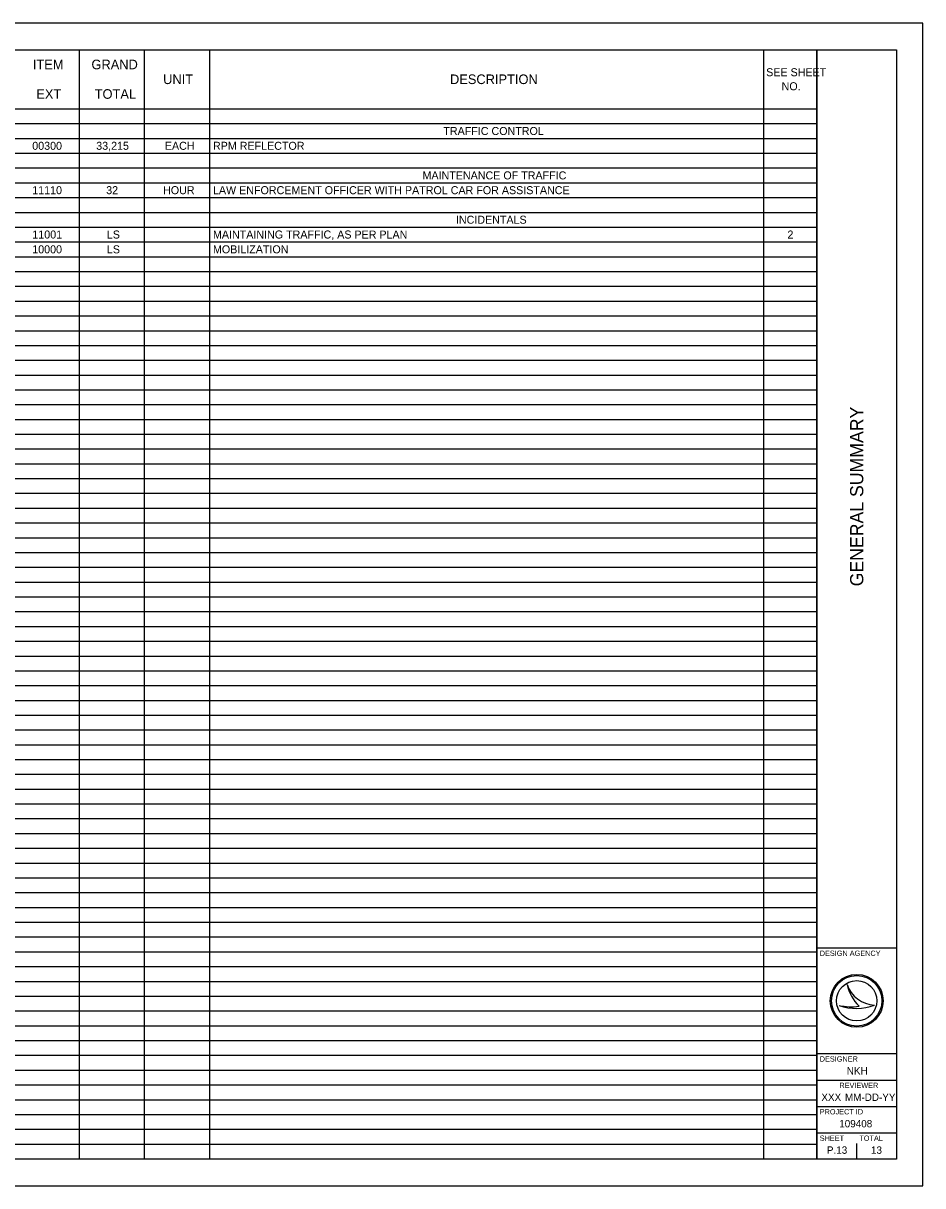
# Model space of a CAD drawing. Extents: x 0 to 34, y 0 to 22.
# Drawn here: x 16.97 to 34, y 0 to 22 of the extents above; entities that cross this region are included whole.
import ezdxf

# ---------------------------------------------------------------- set-up
doc = ezdxf.new("R2010")
doc.units = 0
for name, color, linetype in [('Default', 7, 'Continuous'), ('SH_Border', 7, 'Continuous'), ('SH_Cut_Line', 7, 'Continuous'), ('SH_Data', 7, 'Continuous')]:
    doc.layers.add(name, color=color, linetype=linetype)

msp = doc.modelspace()

# ---------------------------------------------------------------- linework, layer by layer
at = {"layer": 'Default'}
for p, q in [((1.5, 21.5), (31.99, 21.5)), ((18.029, 21.5), (18.029, 0.51)), ((19.264, 21.5), (19.264, 0.51)), ((20.498, 21.5), (20.498, 0.51)), ((30.985, 21.5), (30.985, 0.51)), ((31.99, 21.5), (31.99, 0.51)), ((1.5, 20.381), (31.99, 20.381)), ((1.5, 20.101), (31.99, 20.101)), ((1.5, 19.821), (31.99, 19.821)), ((1.5, 19.541), (31.99, 19.541)), ((1.5, 19.261), (31.99, 19.261)), ((1.5, 18.981), (31.99, 18.981)), ((1.5, 18.701), (31.99, 18.701)), ((1.5, 18.421), (31.99, 18.421)), ((1.5, 18.142), (31.99, 18.142)), ((1.5, 17.862), (31.99, 17.862)), ((1.5, 17.582), (31.99, 17.582)), ((1.5, 17.302), (31.99, 17.302)), ((1.5, 17.022), (31.99, 17.022)), ((1.5, 16.742), (31.99, 16.742)), ((1.5, 16.462), (31.99, 16.462)), ((1.5, 16.182), (31.99, 16.182)), ((1.5, 15.903), (31.99, 15.903)), ((1.5, 15.623), (31.99, 15.623)), ((1.5, 15.343), (31.99, 15.343)), ((1.5, 15.063), (31.99, 15.063)), ((1.5, 14.783), (31.99, 14.783)), ((1.5, 14.503), (31.99, 14.503)), ((1.5, 14.223), (31.99, 14.223)), ((1.5, 13.943), (31.99, 13.943)), ((1.5, 13.664), (31.99, 13.664)), ((1.5, 13.384), (31.99, 13.384)), ((1.5, 13.104), (31.99, 13.104)), ((1.5, 12.824), (31.99, 12.824)), ((1.5, 12.544), (31.99, 12.544)), ((1.5, 12.264), (31.99, 12.264)), ((1.5, 11.984), (31.99, 11.984)), ((1.5, 11.705), (31.99, 11.705)), ((1.5, 11.425), (31.99, 11.425)), ((1.5, 11.145), (31.99, 11.145)), ((1.5, 10.865), (31.99, 10.865)), ((1.5, 10.585), (31.99, 10.585)), ((1.5, 10.305), (31.99, 10.305)), ((1.5, 10.025), (31.99, 10.025)), ((1.5, 9.745), (31.99, 9.745)), ((1.5, 9.466), (31.99, 9.466)), ((1.5, 9.186), (31.99, 9.186)), ((1.5, 8.906), (31.99, 8.906)), ((1.5, 8.626), (31.99, 8.626)), ((1.5, 8.346), (31.99, 8.346)), ((1.5, 8.066), (31.99, 8.066)), ((1.5, 7.786), (31.99, 7.786)), ((1.5, 7.506), (31.99, 7.506)), ((1.5, 7.227), (31.99, 7.227)), ((1.5, 6.947), (31.99, 6.947)), ((1.5, 6.667), (31.99, 6.667)), ((1.5, 6.387), (31.99, 6.387)), ((1.5, 6.107), (31.99, 6.107)), ((1.5, 5.827), (31.99, 5.827)), ((1.5, 5.547), (31.99, 5.547)), ((1.5, 5.267), (31.99, 5.267)), ((1.5, 4.988), (31.99, 4.988)), ((1.5, 4.708), (31.99, 4.708)), ((1.5, 4.428), (31.99, 4.428)), ((1.5, 4.148), (31.99, 4.148)), ((1.5, 3.868), (31.99, 3.868)), ((1.5, 3.588), (31.99, 3.588)), ((1.5, 3.308), (31.99, 3.308)), ((1.5, 3.028), (31.99, 3.028)), ((1.5, 2.749), (31.99, 2.749)), ((1.5, 2.469), (31.99, 2.469)), ((1.5, 2.189), (31.99, 2.189)), ((1.5, 1.909), (31.99, 1.909)), ((1.5, 1.629), (31.99, 1.629)), ((1.5, 1.349), (31.99, 1.349)), ((1.5, 1.069), (31.99, 1.069)), ((1.5, 0.79), (31.99, 0.79)), ((1.5, 0.51), (31.99, 0.51))]:
    msp.add_line(p, q, dxfattribs=at)
at = {"layer": 'SH_Border'}
for p, q in [((32, 0.5), (32, 21.5)), ((32, 4.5), (33.5, 4.5)), ((32, 2.5), (33.5, 2.5)), ((32, 2), (33.5, 2)), ((32, 1.5), (33.5, 1.5)), ((32, 1), (33.5, 1))]:
    msp.add_line(p, q, dxfattribs=at)
msp.add_lwpolyline([(1.5, 21.5), (33.5, 21.5), (33.5, 0.5), (1.5, 0.5)], close=True, dxfattribs=at)
at = {"layer": 'SH_Cut_Line'}
msp.add_lwpolyline([(0, 0), (34, 0), (34, 22), (0, 22)], close=True, dxfattribs=at)
at = {"layer": 'SH_Data'}
for p, q in [((32.567, 3.81), (32.567, 3.81)), ((32.417, 3.41), (32.417, 3.41)), ((32.75, 3.5), (32.75, 3.5)), ((33.087, 3.419), (33.087, 3.419)), ((32.375, 0.675), (32.375, 0.675)), ((32.75, 0.5), (32.75, 0.8))]:
    msp.add_line(p, q, dxfattribs=at)
for radius in [0.5, 0.477, 0.477, 0.382]:
    msp.add_circle((32.75, 3.5), radius, dxfattribs=at)
for centre, radius, start, end in [((33.116, 3.998), 0.58, 198.9257, 198.9319), ((33.347, 3.97), 0.796, 191.6379, 191.6421), ((33.116, 3.998), 0.58, 198.9319, 267.1657), ((33.347, 3.97), 0.796, 191.6421, 226.0947), ((32.739, 4.37), 1.013, 251.4576, 290.0832), ((32.648, 4.654), 1.266, 259.4964, 259.4995), ((32.739, 4.37), 1.013, 251.4527, 251.4576), ((32.648, 4.654), 1.266, 259.4995, 276.6672)]:
    msp.add_arc(centre, radius, start, end, dxfattribs=at)

# ---------------------------------------------------------------- texts
at = {"layer": 'Default'}
for s, height, p in [('ITEM', 0.1818, (17.154, 21.129)), ('GRAND', 0.1818, (18.264, 21.129)), ('SEE SHEET ', 0.1515, (31.036, 20.997)), ('UNIT', 0.1818, (19.621, 20.849)), ('DESCRIPTION', 0.18175, (25.051, 20.849)), ('EXT', 0.1818, (17.22, 20.57)), ('TOTAL', 0.1818, (18.325, 20.57)), ('NO.', 0.1515, (31.328, 20.732)), ('TRAFFIC CONTROL', 0.15146, (24.925, 19.885)), ('00300', 0.1515, (17.143, 19.605)), ('33,215', 0.1515, (18.354, 19.605)), ('EACH', 0.1515, (19.653, 19.605)), ('RPM REFLECTOR', 0.15146, (20.564, 19.605)), ('MAINTENANCE OF TRAFFIC', 0.15146, (24.531, 19.045)), ('11110', 0.1515, (17.143, 18.765)), ('32', 0.1515, (18.543, 18.765)), ('HOUR', 0.1515, (19.62, 18.765)), ('LAW ENFORCEMENT OFFICER WITH PATROL CAR FOR ASSISTANCE', 0.15146, (20.564, 18.765)), ('INCIDENTALS', 0.15146, (25.163, 18.206)), ('11001', 0.1515, (17.145, 17.926)), ('LS', 0.1515, (18.556, 17.926)), ('MAINTAINING TRAFFIC, AS PER PLAN', 0.15146, (20.564, 17.926)), ('2', 0.151, (31.439, 17.926)), ('10000', 0.1515, (17.143, 17.646)), ('LS', 0.1515, (18.556, 17.646)), ('MOBILIZATION', 0.15146, (20.564, 17.646))]:
    msp.add_text(s, height=height, dxfattribs=at).set_placement(p)
at = {"layer": 'SH_Data'}
msp.add_text('GENERAL SUMMARY', height=0.25, rotation=90, dxfattribs=at).set_placement((32.875, 11.344))
for s, height, p in [('DESIGN AGENCY', 0.1, (32.05, 4.35)), ('DESIGNER', 0.1, (32.05, 2.35)), ('NKH', 0.14, (32.562, 2.105)), ('REVIEWER', 0.1, (32.422, 1.85)), ('XXX', 0.14, (32.081, 1.605)), ('MM-DD-YY', 0.14, (32.527, 1.605)), ('PROJECT ID', 0.1, (32.05, 1.35)), ('109408', 0.14, (32.419, 1.105)), ('SHEET', 0.1, (32.05, 0.85)), ('TOTAL', 0.1, (32.8, 0.85)), ('P.13', 0.14, (32.185, 0.605)), ('13', 0.14, (33.02, 0.605))]:
    msp.add_text(s, height=height, dxfattribs=at).set_placement(p)

doc.saveas('drawing.dxf')
